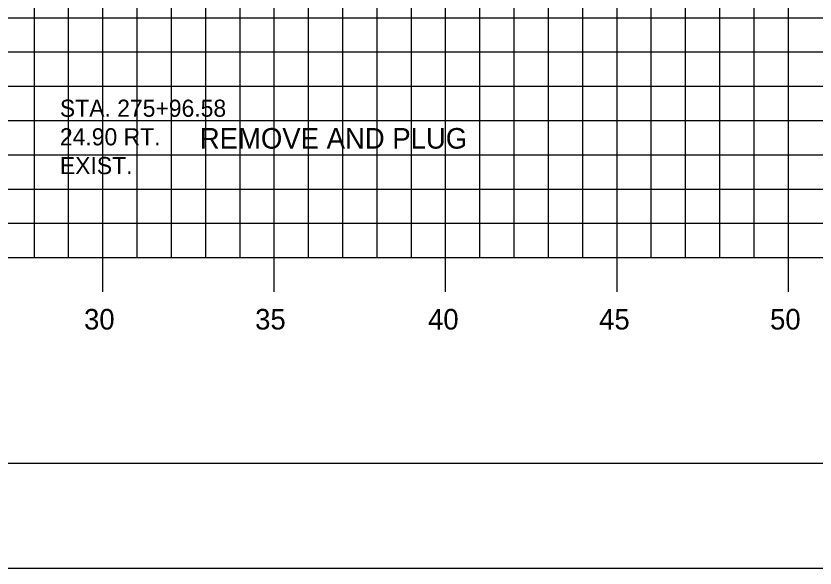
# Model space of a CAD drawing. Extents: x 853785 to 853955, y 366268 to 366378.
# Drawn here: x 853895.9 to 853919.21, y 366268.18 to 366284.29 of the extents above; entities that cross this region are included whole.
import ezdxf

# ---------------------------------------------------------------- set-up
doc = ezdxf.new("R2010")
doc.units = 0
for name, color, linetype in [('BORDER', 7, 'Continuous'), ('D_Text_Monospaced', 7, 'Continuous'), ('D_Text_Standard', 7, 'Continuous'), ('H_V ANNOTATION', 7, 'Continuous'), ('MAJOR', 7, 'Continuous'), ('MINOR', 7, 'Continuous'), ('PLOT BOUNDARY', 7, 'Continuous')]:
    doc.layers.add(name, color=color, linetype=linetype)

msp = doc.modelspace()

# ---------------------------------------------------------------- linework, layer by layer
at = {"layer": 'BORDER'}
msp.add_line((853793.435, 366271.236), (853953.435, 366271.236), dxfattribs=at)
at = {"layer": 'MAJOR'}
for p, q in [((853898.435, 366277.236), (853898.435, 366297.236)), ((853903.435, 366277.236), (853903.435, 366297.236)), ((853908.435, 366277.236), (853908.435, 366297.236)), ((853913.435, 366277.236), (853913.435, 366297.236)), ((853918.435, 366277.236), (853918.435, 366297.236)), ((853798.435, 366282.236), (853938.435, 366282.236)), ((853798.435, 366277.236), (853938.435, 366277.236)), ((853798.435, 366277.236), (853938.435, 366277.236)), ((853898.435, 366276.234), (853898.435, 366277.236)), ((853903.435, 366276.234), (853903.435, 366277.236)), ((853908.435, 366276.234), (853908.435, 366277.236)), ((853913.435, 366276.234), (853913.435, 366277.236)), ((853918.435, 366276.234), (853918.435, 366277.236))]:
    msp.add_line(p, q, dxfattribs=at)
at = {"layer": 'MINOR'}
for p, q in [((853896.435, 366277.236), (853896.435, 366297.236)), ((853897.435, 366277.236), (853897.435, 366297.236)), ((853899.435, 366277.236), (853899.435, 366297.236)), ((853900.435, 366277.236), (853900.435, 366297.236)), ((853901.435, 366277.236), (853901.435, 366297.236)), ((853902.435, 366277.236), (853902.435, 366297.236)), ((853904.435, 366277.236), (853904.435, 366297.236)), ((853905.435, 366277.236), (853905.435, 366297.236)), ((853906.435, 366277.236), (853906.435, 366297.236)), ((853907.435, 366277.236), (853907.435, 366297.236)), ((853909.435, 366277.236), (853909.435, 366297.236)), ((853910.435, 366277.236), (853910.435, 366297.236)), ((853911.435, 366277.236), (853911.435, 366297.236)), ((853912.435, 366277.236), (853912.435, 366297.236)), ((853914.435, 366277.236), (853914.435, 366297.236)), ((853915.435, 366277.236), (853915.435, 366297.236)), ((853916.435, 366277.236), (853916.435, 366297.236)), ((853917.435, 366277.236), (853917.435, 366297.236)), ((853798.435, 366284.236), (853938.435, 366284.236)), ((853798.435, 366283.236), (853938.435, 366283.236)), ((853798.435, 366281.236), (853938.435, 366281.236)), ((853798.435, 366280.236), (853938.435, 366280.236)), ((853798.435, 366279.236), (853938.435, 366279.236)), ((853798.435, 366278.236), (853938.435, 366278.236))]:
    msp.add_line(p, q, dxfattribs=at)
at = {"layer": 'PLOT BOUNDARY'}
msp.add_lwpolyline([(853785.342, 366268.177), (853955.342, 366268.177), (853955.342, 366378.177), (853785.342, 366378.177)], close=True, dxfattribs=at)

# ---------------------------------------------------------------- texts
at = {"layer": 'D_Text_Monospaced'}
for s, height, p in [('STA. 275+96.58', 0.49998, (853897.18, 366281.344)), ('24.90 RT.', 0.5, (853897.18, 366280.51)), ('EXIST. ', 0.5, (853897.18, 366279.67))]:
    msp.add_text(s, height=height, dxfattribs=at).set_placement(p)
at = {"layer": 'D_Text_Standard'}
msp.add_text('REMOVE AND PLUG', height=0.6, dxfattribs=at).set_placement((853901.262, 366280.415))
at = {"layer": 'H_V ANNOTATION'}
for s, p in [('30', (853897.884, 366275.136)), ('35', (853902.876, 366275.136)), ('40', (853907.921, 366275.136)), ('45', (853912.913, 366275.136)), ('50', (853917.9, 366275.136))]:
    msp.add_text(s, height=0.6, dxfattribs=at).set_placement(p)

doc.saveas('drawing.dxf')
